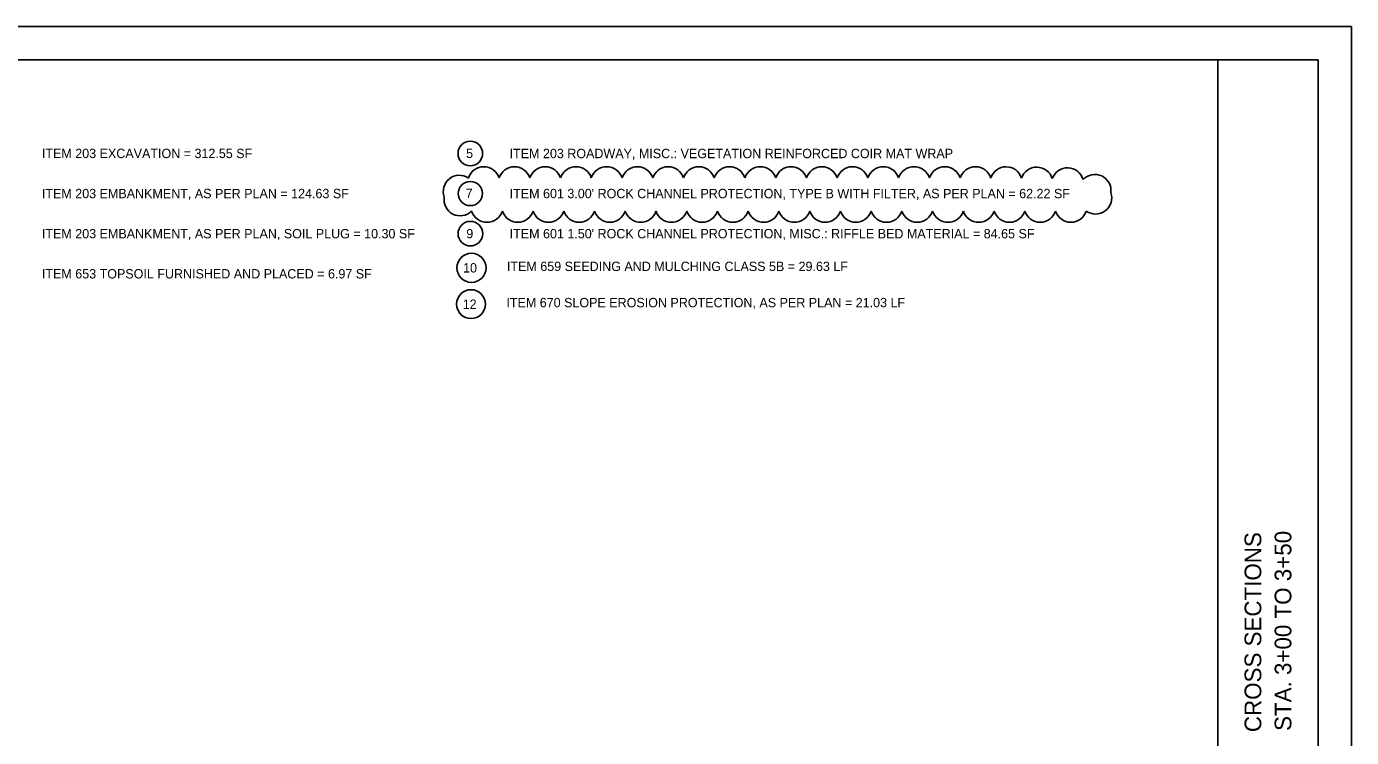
# Model space of a CAD drawing. Extents: x -34.1 to 34, y 0 to 22.
# Drawn here: x 14.17 to 34, y 11.37 to 22 of the extents above; entities that cross this region are included whole.
import ezdxf

# ---------------------------------------------------------------- set-up
doc = ezdxf.new("R2010")
doc.units = 0
for name, color, linetype in [('CS-ALGN-TEXT', 7, 'Continuous'), ('CS-ANNO', 7, 'Continuous'), ('CS-ANNO-MATC', 7, 'Continuous'), ('CS-ANNO-MATC-TEXT', 7, 'Continuous')]:
    doc.layers.add(name, color=color, linetype=linetype)

msp = doc.modelspace()

# ---------------------------------------------------------------- linework, layer by layer
at = {"layer": 'CS-ALGN-TEXT'}
for centre, start, end in [((21.014, 19.662), 17.5, 162.5), ((21.474, 19.662), 17.5, 162.5), ((21.934, 19.662), 17.5, 162.5), ((22.394, 19.662), 17.5, 162.5), ((22.854, 19.662), 17.5, 162.5), ((23.314, 19.662), 17.5, 162.5), ((23.774, 19.662), 17.5, 162.5), ((24.233, 19.662), 17.5, 162.5), ((24.693, 19.662), 17.5, 162.5), ((25.153, 19.662), 17.5, 162.5), ((25.613, 19.662), 17.5, 162.5), ((26.073, 19.662), 17.5, 162.5), ((26.533, 19.662), 17.5, 162.5), ((26.993, 19.662), 17.5, 162.5), ((27.453, 19.662), 17.5, 162.5), ((27.913, 19.662), 17.5, 162.5), ((28.373, 19.662), 17.4568, 162.4568), ((28.832, 19.661), 17.1962, 162.1962), ((29.291, 19.656), 16.7309, 161.7309), ((29.75, 19.646), 15.6355, 160.6355), ((20.649, 19.535), 55.7637, 200.7637), ((30.16, 19.547), 352.4275, 137.4275), ((20.661, 19.41), 170.4412, 315.4412), ((30.171, 19.436), 234.2529, 19.2529), ((21.063, 19.313), 197.5, 342.5), ((21.523, 19.313), 197.5, 342.5), ((21.982, 19.313), 197.5, 342.5), ((22.442, 19.313), 197.5, 342.5), ((22.902, 19.313), 197.5, 342.5), ((23.362, 19.313), 197.5, 342.5), ((23.822, 19.313), 197.5, 342.5), ((24.282, 19.313), 197.5, 342.5), ((24.742, 19.313), 197.5, 342.5), ((25.202, 19.313), 197.5, 342.5), ((25.662, 19.313), 197.5, 342.5), ((26.122, 19.313), 197.5, 342.5), ((26.581, 19.313), 197.5, 342.5), ((27.041, 19.313), 197.5, 342.5), ((27.501, 19.313), 197.5, 342.5), ((27.961, 19.313), 197.5, 342.5), ((28.421, 19.313), 197.5, 342.5), ((28.881, 19.313), 197.5, 342.5), ((29.341, 19.313), 197.5, 342.5), ((29.801, 19.313), 197.5, 342.5)]:
    msp.add_arc(centre, 0.241, start, end, dxfattribs=at)
at = {"layer": 'CS-ANNO'}
msp.add_lwpolyline([(0, 0), (34, 0), (34, 22), (0, 22)], close=True, dxfattribs=at)
at = {"layer": 'CS-ANNO-MATC'}
msp.add_line((32, 0.5), (32, 21.5), dxfattribs=at)
msp.add_lwpolyline([(1.5, 21.5), (33.5, 21.5), (33.5, 0.5), (1.5, 0.5)], close=True, dxfattribs=at)
at = {"layer": 'CS-ANNO-MATC-TEXT'}
for centre, radius in [((20.813, 20.101), 0.184), ((20.813, 19.502), 0.181), ((20.814, 18.902), 0.184), ((20.83, 18.39), 0.218), ((20.823, 17.848), 0.216)]:
    msp.add_circle(centre, radius, dxfattribs=at)

# ---------------------------------------------------------------- texts
at = {"layer": 'CS-ALGN-TEXT'}
for s, p in [('CROSS SECTIONS', (32.65, 11.447)), ('STA. 3+00 TO 3+50', (33.1, 11.465))]:
    msp.add_text(s, height=0.25, rotation=90, dxfattribs=at).set_placement(p)
at = {"layer": 'CS-ANNO-MATC-TEXT'}
for s, p in [('ITEM 203 EXCAVATION = 312.55 SF', (14.402, 20.032)), ('5', (20.75, 20.033)), ('ITEM 203 ROADWAY, MISC.: VEGETATION REINFORCED COIR MAT WRAP', (21.401, 20.031)), ('ITEM 203 EMBANKMENT, AS PER PLAN = 124.63 SF', (14.402, 19.432)), ('7', (20.743, 19.433)), ("ITEM 601 3.00' ROCK CHANNEL PROTECTION, TYPE B WITH FILTER, AS PER PLAN = 62.22 SF", (21.402, 19.432)), ('ITEM 203 EMBANKMENT, AS PER PLAN, SOIL PLUG = 10.30 SF', (14.402, 18.832)), ('9', (20.753, 18.832)), ("ITEM 601 1.50' ROCK CHANNEL PROTECTION, MISC.: RIFFLE BED MATERIAL = 84.65 SF", (21.402, 18.832)), ('10', (20.705, 18.321)), ('ITEM 659 SEEDING AND MULCHING CLASS 5B = 29.63 LF', (21.361, 18.343)), ('ITEM 653 TOPSOIL FURNISHED AND PLACED = 6.97 SF', (14.402, 18.232)), ('12', (20.699, 17.777)), ('ITEM 670 SLOPE EROSION PROTECTION, AS PER PLAN = 21.03 LF', (21.353, 17.801))]:
    msp.add_text(s, height=0.14, dxfattribs=at).set_placement(p)

doc.saveas('drawing.dxf')
